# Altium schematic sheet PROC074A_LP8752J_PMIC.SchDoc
size 431 x 279 mm; Date: Not shown in title block; ApprovedBy: Not shown in title block; CheckedBy: Not shown in title block; Author: Not shown in title block; CompanyName: Not shown in title block; Engineer: Not shown in title block; Organization: Not shown in title block; Address1: Not shown in title block; Address2: Not shown in title block; Address3: Not shown in title block; Address4: Not shown in title block; DocumentNumber: 1; Revision: Use project parameter SCH_Rev; SheetNumber: 7; SheetTotal: 22; PageSetup: Record=PageOptions¦CenterHorizontal=True¦CenterVertical=True¦PrintScale=1.00¦XCorrection=1.00¦YCorrection=1.00¦PrintKind=0¦BorderSize=5000000¦LeftOffset=0¦BottomOffset=0¦Orientation=2¦PaperLength=1000¦PaperWidth=1000¦Scale=100¦PaperSource=15¦PrintQuality=600¦MediaType=1¦DitherType=10¦PaperKind=Letter¦PrintScaleMode=1
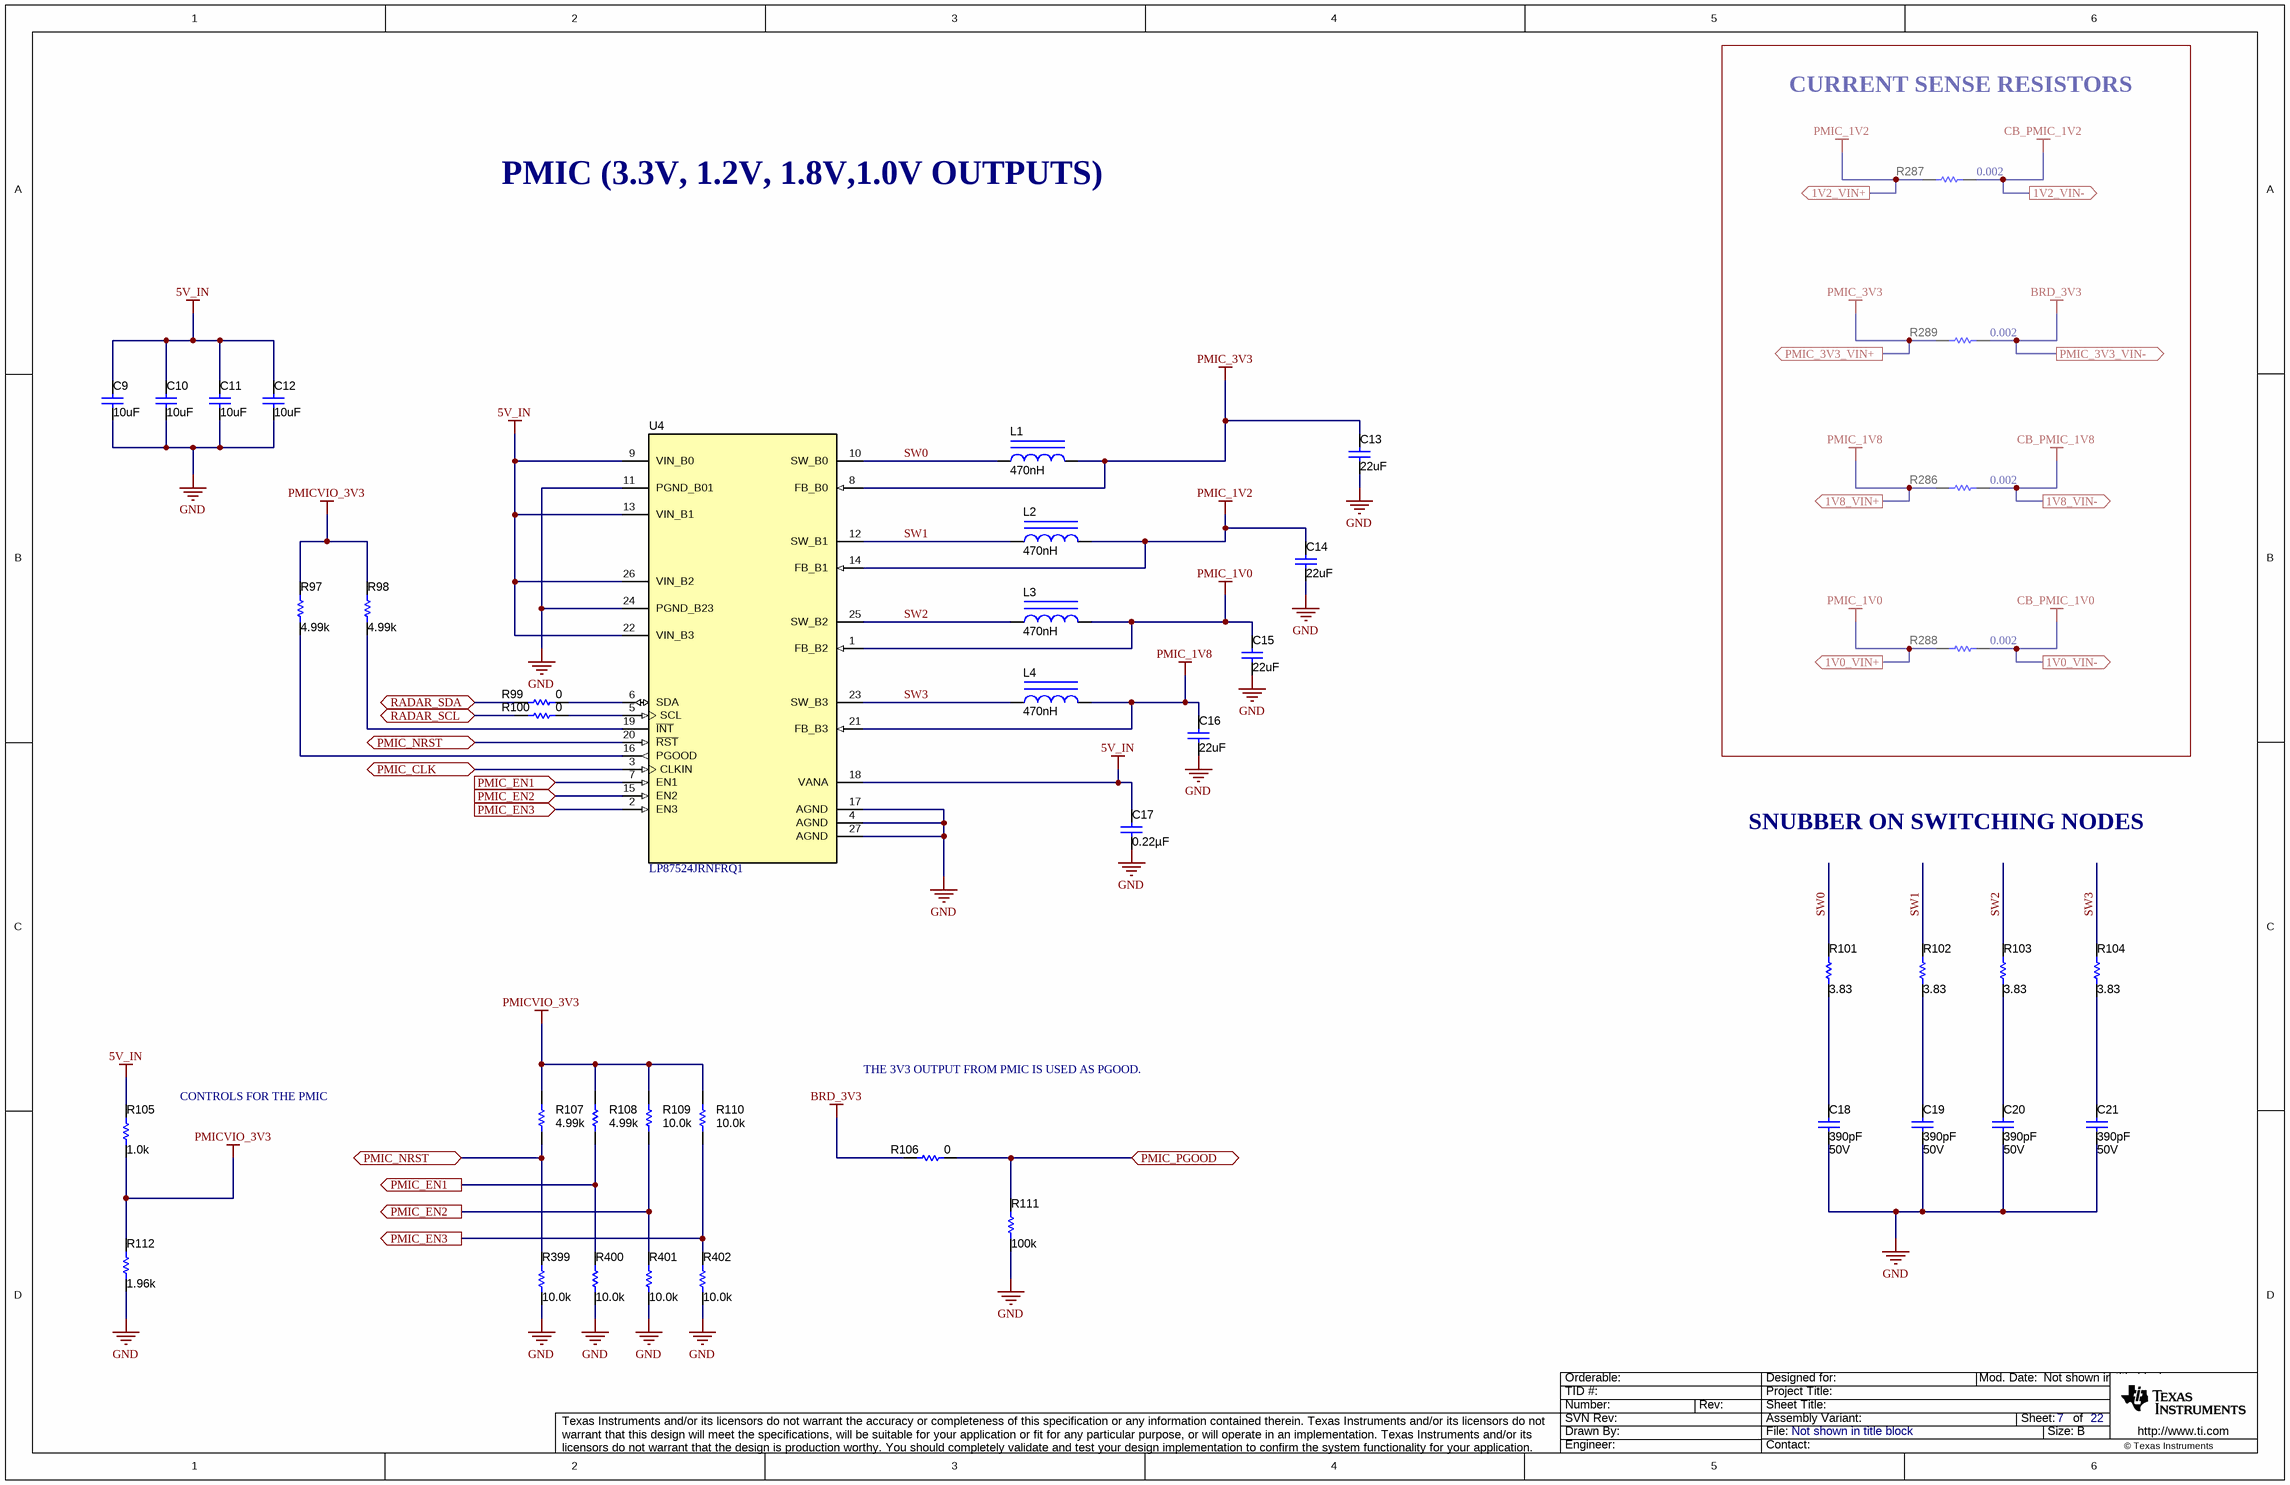
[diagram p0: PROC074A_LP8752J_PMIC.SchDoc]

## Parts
C9  ValueDisplayed: 10uF  [0805_HV]  (hidden comment: GCM21BR71A106KE22L)
C10  ValueDisplayed: 10uF  [0805_HV]  (hidden comment: GCM21BR71A106KE22L)
C11  ValueDisplayed: 10uF  [0805_HV]  (hidden comment: GCM21BR71A106KE22L)
C12  ValueDisplayed: 10uF  [0805_HV]  (hidden comment: GCM21BR71A106KE22L)
C13  ValueDisplayed: 22uF  [1206_180]  (hidden comment: GCM31CR71A226KE02)
C14  ValueDisplayed: 22uF  [1206_180]  (hidden comment: GCM31CR71A226KE02)
C15  ValueDisplayed: 22uF  [1206_180]  (hidden comment: GCM31CR71A226KE02)
C16  ValueDisplayed: 22uF  [1206_180]  (hidden comment: GCM31CR71A226KE02)
C17  ValueDisplayed: 0.22µF  [0402L]  (hidden comment: GCM155R71C224KE02D)
C18  VDC_V: 50V  ValueDisplayed: 390pF  [0402L]  (hidden comment: CGA2B2NP01H391J050BA)
C19  VDC_V: 50V  ValueDisplayed: 390pF  [0402L]  (hidden comment: CGA2B2NP01H391J050BA)
C20  VDC_V: 50V  ValueDisplayed: 390pF  [0402L]  (hidden comment: CGA2B2NP01H391J050BA)
C21  VDC_V: 50V  ValueDisplayed: 390pF  [0402L]  (hidden comment: CGA2B2NP01H391J050BA)
L1  ValueDisplayed: 470nH  [DFE252012P]  (hidden comment: DFE252012P-R47M=P2)
L2  ValueDisplayed: 470nH  [DFE252012P]  (hidden comment: DFE252012P-R47M=P2)
L3  ValueDisplayed: 470nH  [DFE252012P]  (hidden comment: DFE252012P-R47M=P2)
L4  ValueDisplayed: 470nH  [DFE252012P]  (hidden comment: DFE252012P-R47M=P2)
R97  ValueDisplayed: 4.99k  [0402L]  (hidden comment: CRCW04024K99FKED)
R98  ValueDisplayed: 4.99k  [0402L]  (hidden comment: CRCW04024K99FKED)
R99  ValueDisplayed: 0  [0201_Silk]  (hidden comment: CRCW02010000Z0ED)
R100  ValueDisplayed: 0  [0201_Silk]  (hidden comment: CRCW02010000Z0ED)
R101  ValueDisplayed: 3.83  [0402L]  (hidden comment: CRCW04023R83FKED)
R102  ValueDisplayed: 3.83  [0402L]  (hidden comment: CRCW04023R83FKED)
R103  ValueDisplayed: 3.83  [0402L]  (hidden comment: CRCW04023R83FKED)
R104  ValueDisplayed: 3.83  [0402L]  (hidden comment: CRCW04023R83FKED)
R105  ValueDisplayed: 1.0k  [0402L]  (hidden comment: ERJ-2GEJ102X)
R106  ValueDisplayed: 0  [0402L]  (hidden comment: ERJ-2GE0R00X)
R107  ValueDisplayed: 4.99k  [0402L]  (hidden comment: ERJ-2RKF4991X)
R108  ValueDisplayed: 4.99k  [0402L]  (hidden comment: ERJ-2RKF4991X)
R109  ValueDisplayed: 10.0k  [0402L]  (hidden comment: CRCW040210K0FKED)
R110  ValueDisplayed: 10.0k  [0402L]  (hidden comment: CRCW040210K0FKED)
R111  ValueDisplayed: 100k  [0402L]  (hidden comment: CRCW0402100KFKED)
R112  ValueDisplayed: 1.96k  [0402L]  (hidden comment: CRCW04021K96FKED)
R286  ValueDisplayed: 0.002  [1206]  (hidden comment: PMR18EZPFV2L00)
R287  ValueDisplayed: 0.002  [1206]  (hidden comment: PMR18EZPFV2L00)
R288  ValueDisplayed: 0.002  [1206]  (hidden comment: PMR18EZPFV2L00)
R289  ValueDisplayed: 0.002  [1206]  (hidden comment: PMR18EZPFV2L00)
R399  ValueDisplayed: 10.0k  [0402L]  (hidden comment: CRCW040210K0FKED)
R400  ValueDisplayed: 10.0k  [0402L]  (hidden comment: CRCW040210K0FKED)
R401  ValueDisplayed: 10.0k  [0402L]  (hidden comment: CRCW040210K0FKED)
R402  ValueDisplayed: 10.0k  [0402L]  (hidden comment: CRCW040210K0FKED)
U4  LP87524JRNFRQ1  [RNF0026C]

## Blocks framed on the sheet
CURRENT SENSE RESISTORS: R286-R289

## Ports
1V0_VIN+ (out), 1V0_VIN- (out), 1V2_VIN+ (out), 1V2_VIN- (out), 1V8_VIN+ (out), 1V8_VIN- (out), PMIC_3V3_VIN+ (out), PMIC_3V3_VIN- (out), PMIC_CLK, PMIC_EN1 (in), PMIC_EN1 (out), PMIC_EN2 (in), PMIC_EN2 (out), PMIC_EN3 (in), PMIC_EN3 (out), PMIC_NRST, PMIC_PGOOD, RADAR_SCL, RADAR_SDA

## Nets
5V_IN: C9.2 C10.2 C11.2 C12.2 C17.2 R105.2 U4.9(VIN_B0) U4.13(VIN_B1) U4.18(VANA) U4.22(VIN_B3) U4.26(VIN_B2)
BRD_3V3: R106.1 R289.2 ; port PMIC_3V3_VIN-
CB_PMIC_1V0: R288.2 ; port 1V0_VIN-
CB_PMIC_1V2: R287.2 ; port 1V2_VIN-
CB_PMIC_1V8: R286.2 ; port 1V8_VIN-
GND: C9.1 C10.1 C11.1 C12.1 C13.1 C14.1 C15.1 C16.1 C17.1 C18.1 C19.1 C20.1 C21.1 R111.1 R112.1 R399.1 R400.1 R401.1 R402.1 U4.4(AGND) U4.11(PGND_B01) U4.17(AGND) U4.24(PGND_B23) U4.27(AGND)
PMIC_1V0: C15.2 L3.2 R288.1 U4.1(FB_B2) ; port 1V0_VIN+
PMIC_1V2: C14.2 L2.2 R287.1 U4.14(FB_B1) ; port 1V2_VIN+
PMIC_1V8: C16.2 L4.2 R286.1 U4.21(FB_B3) ; port 1V8_VIN+
PMIC_3V3: C13.2 L1.2 R289.1 U4.8(FB_B0) ; port PMIC_3V3_VIN+
PMICVIO_3V3: R97.2 R98.2 R105.1 R107.1 R108.2 R109.2 R110.2 R112.2
PMIC_CLK: U4.3(CLKIN) ; port PMIC_CLK
PMIC_EN1: R108.1 R400.2 U4.7(EN1) ; port PMIC_EN1
PMIC_EN2: R109.1 R401.2 U4.15(EN2) ; port PMIC_EN2
PMIC_EN3: R110.1 R402.2 U4.2(EN3) ; port PMIC_EN3
PMIC_NRST: R107.2 R399.2 U4.20(~{RST}) ; port PMIC_NRST
PMIC_PGOOD: R106.2 R111.2 ; port PMIC_PGOOD
RADAR_SCL: R100.2 ; port RADAR_SCL
RADAR_SDA: R99.2 ; port RADAR_SDA
SW0: L1.1 R101.2 U4.10(SW_B0)
SW1: L2.1 R102.2 U4.12(SW_B1)
SW2: L3.1 R103.2 U4.25(SW_B2)
SW3: L4.1 R104.2 U4.23(SW_B3)
NetC18_2: C18.2 R101.1
NetC19_2: C19.2 R102.1
NetC20_2: C20.2 R103.1
NetC21_2: C21.2 R104.1
NetR97_1: R97.1 U4.16(PGOOD)
NetR98_1: R98.1 U4.19(~{INT})
NetR99_1: R99.1 U4.6(SDA)
NetR100_1: R100.1 U4.5(SCL)

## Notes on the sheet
- PMIC (3.3V, 1.2V, 1.8V,1.0V OUTPUTS)
- SNUBBER ON SWITCHING NODES
- CONTROLS FOR THE PMIC
- THE 3V3 OUTPUT FROM PMIC IS USED AS PGOOD.

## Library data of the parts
C9-C12 = CMP-0008017-2: CAP, CERM, 10 uF, 10 V, +/- 10%, X7R, 0805; Manufacturer: MuRata; TaMin_C: -55°C; Polarized: N; SizeAreaWB_mm2: 6.75; Value1: Unknown; U/M: EA; Value: 10uF; TaMax_C: 125°C; SizeZ_mm: 1.45; SizeX_mm: 2; SizeY_mm: 1.25; Cap_Case: 0805; Value2: 10V; SizeArea_mm2: 2.5; CompType: Capacitor; Cap_F: 10µF; AEC Category: Q200
C13-C16 = CMP-0008811-2: CAP, CERM, 22 uF, 10 V, +/- 10%, X7R, AEC-Q200 Grade 1, 1206; Manufacturer: MuRata; TaMin_C: -55°C; Polarized: N; SizeAreaWB_mm2: 10.92; Value1: Unknown; U/M: EA; Value: 22uF; TaMax_C: 125°C; SizeZ_mm: 1.8; SizeX_mm: 3.2; SizeY_mm: 1.6; Cap_Case: 1206; Value2: 10V; SizeArea_mm2: 5.12; CompType: Capacitor; AEC Qualified: Y; Cap_F: 22µF; AEC Grade: 1; AEC Category: Q200
C17 = CMP-0078265-1: CAP, CERM, 0.22 µF, 16 V,+/- 10%, X7R, AEC-Q200 Grade 1, 0402; Manufacturer: MuRata; TaMin_C: -55°C; Polarized: N; SizeAreaWB_mm2: 3; U/M: EA; Value: 0.22uF; TaMax_C: 125°C; SizeZ_mm: 0.6; SizeX_mm: 1; SizeY_mm: 0.5; Cap_Case: 0402; Value2: 16V; CompType: Capacitor; AEC Qualified: Y; Cap_F: 220nF; AEC Category: Q200
C18-C21 = CMP-0078223-1: CAP, CERM, 390 pF, 50 V,+/- 5%, C0G/NP0, AEC-Q200 Grade 0, 0402; Manufacturer: TDK; TaMin_C: -55°C; Polarized: N; SizeAreaWB_mm2: 3; U/M: EA; Value: 390pF; TaMax_C: 150°C; SizeZ_mm: 0.6; SizeX_mm: 1; SizeY_mm: 0.5; Cap_Case: 0402; AEC Qualified: Y; AEC Grade: 0; AEC Category: Q200
L1-L4 = CMP-0058946-1: Inductor, Shielded, 470 nH, 4.7 A, 0.021 ohm, SMD; Manufacturer: MuRata Toko; Isat: 6.4A @ 30% inductance drop; Irms: 4.7A @ 40C rise; SizeAreaWB_mm2: 10.5; DCR_ohm: 0.021; Value: 470nH; Imax_A: 4.7A; SizeZ_mm: 1.2; SizeX_mm: 2.5; SizeY_mm: 2; SizeArea_mm2: 5; AEC Category: Q200
R97 R98 = CMP-0026414-1: RES, 4.99 k, 1%, 0.063 W, 0402; Manufacturer: Vishay-Dale; Power_W: 63mW; TempCo: 100 ppm/C; Value_Code: 4k99; U/M: EA; Value: 4.99k; EIA_Code: E96; SizeX_mm: 1; SizeY_mm: 0.5; SizeZ_mm: 0.6; Value2: 0.063W; VDC_V: 50V; AEC Category: Q200
R99 R100 = CMP-0027008-3: RES, 0, 5%, 0.05 W, 0201; Manufacturer: Vishay-Dale; Power_W: 50mW; TempCo: ppm/C; Value_Code: 0000; U/M: EA; Value: 0; EIA_Code: E24; SizeX_mm: 0.6; SizeY_mm: 0.3; SizeZ_mm: 0.26; Value2: 0.05W; SizeArea_mm2: 0.18; AEC Qualified: N; AEC Category: Q200
R101-R104 = CMP-0026363-1: RES, 3.83, 1%, 0.063 W, 0402; Manufacturer: Vishay-Dale; Power_W: 63mW; TempCo: 100 ppm/C; Value_Code: 3R83; U/M: EA; Value: 3.83; EIA_Code: E96; SizeX_mm: 1; SizeY_mm: 0.5; SizeZ_mm: 0.6; Value2: 0.063W; VDC_V: 50V; AEC Category: Q200
R105 = CMP-0078193-1: RES, 1.0 k, 5%, 0.1 W, AEC-Q200 Grade 0, 0402; Manufacturer: Panasonic; Value_Code: 1k00; SizeArea_mm2: 0.5; AEC Qualified: Y; AEC Category: Q200; Res_ohm: 1k; Value: 1.0k; SizeZ_mm: 0.6; Green_REACh: Passed; EIA_Code: E24; TempCo: 200 ppm/C; AEC Grade: 0; Power_W: 100mW; VDC_V: 50V; Value2: 0.1W; Green_Lifecycle: Active; U/M: EA; SizeX_mm: 1
R106 = CMP-0026992-2: RES, 0, 5%, 0.063 W, 0402; Manufacturer: Panasonic; Power_W: 63mW; TempCo: 600 ppm/C; Value_Code: 0000; U/M: EA; Value: 0; EIA_Code: E24; SizeX_mm: 1; SizeY_mm: 0.5; SizeZ_mm: 0.6; Value2: 0.063W; VDC_V: 50V; AEC Category: Q200
R107 R108 = CMP-0026701-1: RES, 4.99 k, 1%, 0.1 W, AEC-Q200 Grade 0, 0402; Manufacturer: Panasonic; Power_W: 100mW; TempCo: 100 ppm/C; Value_Code: 4k99; U/M: EA; Value: 4.99k; EIA_Code: E96; SizeX_mm: 1; SizeY_mm: 0.5; SizeZ_mm: 0.6; Value2: 0.1W; CompType: Resistor; AEC Qualified: Y; VDC_V: 50V; AEC Grade: 0; AEC Category: Q200; INSTALLATION: DNP
R109 R110 = CMP-0025958-2: RES, 10.0 k, 1%, 0.063 W, 0402; Manufacturer: Vishay-Dale; Power_W: 63mW; TempCo: 100 ppm/C; Value_Code: 10k0; U/M: EA; Value: 10.0k; EIA_Code: E96; Res_ohm: 10k; SizeX_mm: 1; SizeY_mm: 0.5; SizeZ_mm: 0.6; Value2: 0.063W; CompType: Resistor; VDC_V: 50V; AEC Category: Q200; INSTALLATION: DNP
R111 = CMP-0025950-2: RES, 100 k, 1%, 0.063 W, 0402; Manufacturer: Vishay-Dale; Power_W: 63mW; TempCo: 100 ppm/C; U/M: EA; Value: 100k; EIA_Code: E96; SizeX_mm: 1; SizeY_mm: 0.5; SizeZ_mm: 0.6; Value2: 0.063W; VDC_V: 50V; AEC Category: Q200
R112 = CMP-0026099-1: RES, 1.96 k, 1%, 0.063 W, 0402; Manufacturer: Vishay-Dale; Power_W: 63mW; TempCo: 100 ppm/C; Value_Code: 1k96; U/M: EA; Value: 1.96k; EIA_Code: E96; SizeX_mm: 1; SizeY_mm: 0.5; SizeZ_mm: 0.6; Value2: 0.063W; CompType: Resistor; VDC_V: 50V; AEC Category: Q200
R286-R289 = CMP-0081623-1: RES, 0.002, 1%, 1 W, AEC-Q200 Grade 0, 1206; Manufacturer: Rohm; Value_Code: 2L000; SizeAreaWB_mm2: 10.92; SizeArea_mm2: 5.12; AEC Qualified: Y; AEC Category: Q200; Res_ohm: 2m; Value: 0.002; SizeZ_mm: 1.35; Green_REACh: Incomplete; TempCo: 100 ppm/C; AEC Grade: 0; Power_W: 1W; SizeY_mm: 1.6; Green_Lifecycle: Active; CompType: Resistor; SizeX_mm: 3.2; INSTALLATION: DNP
R399-R402 = CMP-0025958-2: RES, 10.0 k, 1%, 0.063 W, 0402; Manufacturer: Vishay-Dale; Power_W: 63mW; TempCo: 100 ppm/C; Value_Code: 10k0; U/M: EA; Value: 10.0k; EIA_Code: E96; Res_ohm: 10k; SizeX_mm: 1; SizeY_mm: 0.5; SizeZ_mm: 0.6; Value2: 0.063W; VDC_V: 50V; AEC Category: Q200
U4 = CMP-0079120-1: 4-A + 2.5-A + Two 1.5-A Buck Converters With Integrated Switches, RNF0026C (VQFN-HR-26); Alternate PartNumber: LP87524JRNFTQ1; Alternate Manufacturer: Texas Instruments; SizeAreaWB_mm2: 27.5; SizeZ_mm: 0.9; SizeX_mm: 4; SizeY_mm: 4.5; SizeArea_mm2: 18; CompType: IC; AEC Qualified: Y; AEC Category: Q200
